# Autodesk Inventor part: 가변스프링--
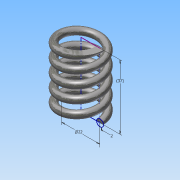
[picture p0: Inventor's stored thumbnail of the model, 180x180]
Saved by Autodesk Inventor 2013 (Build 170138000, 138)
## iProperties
Created: 2016-01
Part Number: 가변스프링--
Material: 스테인리스강
Document SubType Name: Modeling
Designer: Administrator
Mass: 34.2635 g
Surface Area: 43.3242 cm^2
Volume: 4.24053 cm^3
Density: 8.08 g/cm^3
Author: Administrator
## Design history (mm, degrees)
sketch "스케치1"
  geometry: L1 (0, 0)-(11, 0); L2 (11, 0)-(11, 37); L3 (11, 37)-(0, 37); L4 (0, 37)-(0, 0); C1 r 2 at (11, 0)
  constraints: 8 end point, 2 parallel, 1 centre point, 1 coincident, 1 horizontal, 1 perpendicular
  dimensions: "d0" = 2 radius of C1; "d1" = 22 diameter of L2 L4; "d2" = 37 distance between parallel lines of L3 L1 (derived)
feature "코일1" sketch "스케치1" pitch "d3" = 10; turns "d5" = 5; dims "d4" = 37 (= d2), "d6" = 0, angle "d7" = 90 deg, angle "d8" = 90 deg, "d9" = 0, "d10" = 0
feature "분할1"
node "작업 평면1"
feature "분할2"
node "솔리드1"
other parameters: "d11" = 90 deg
